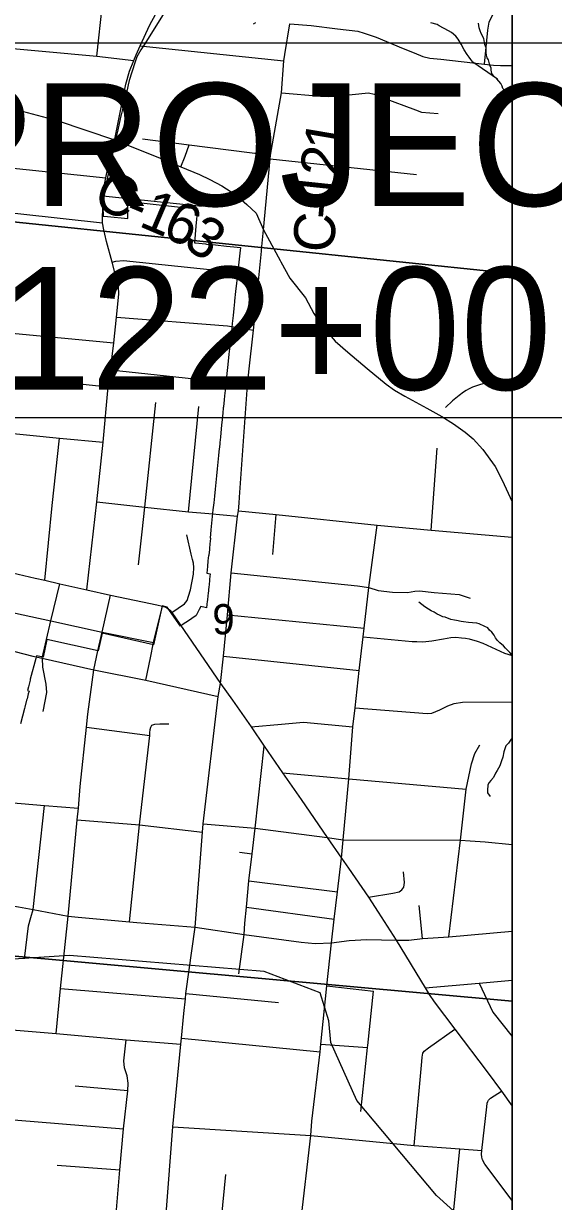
# Model space of a CAD drawing. Extents: x 0 to 43.4, y -8.1 to 22.
# Drawn here: x 8.223 to 8.957, y 18.91 to 20.543 of the extents above; entities that cross this region are included whole.
import ezdxf

# ---------------------------------------------------------------- set-up
doc = ezdxf.new("R2010")
doc.units = 0
for name, color, linetype in [('GM_X_City_Street', 7, 'Continuous'), ('GM_X_Corporation', 7, 'Continuous'), ('GM_X_County_Road', 7, 'Continuous'), ('GM_X_County_Road_Text', 7, 'Continuous'), ('GM_X_Minor_River', 7, 'Continuous'), ('GM_X_Rail_Line', 7, 'Continuous'), ('GM_X_Section_Text', 7, 'Continuous'), ('GM_X_Township_Road', 7, 'Continuous'), ('SH_Data', 7, 'Continuous'), ('SH_Masking', 7, 'Continuous'), ('SH_Text', 7, 'Continuous')]:
    doc.layers.add(name, color=color, linetype=linetype)

msp = doc.modelspace()

# ---------------------------------------------------------------- linework, layer by layer
at = {"layer": 'GM_X_City_Street'}
for p, q in [((8.3245, 20.4975), (8.3324, 20.5696)), ((8.0501, 20.3584), (8.3368, 20.329)), ((8.3516, 20.1358), (8.5054, 20.1236)), ((8.5054, 20.1236), (8.5413, 20.1177)), ((8.2021, 20.114), (8.3479, 20.1001)), ((8.1964, 20.0545), (8.34, 20.0391)), ((8.3432, 20.0626), (8.4985, 20.0459)), ((8.4985, 20.0459), (8.533, 20.0415)), ((8.4516, 19.8661), (8.4658, 20.0117)), ((8.7877, 19.8403), (8.796, 19.9541)), ((8.4796, 19.8636), (8.5194, 19.8601)), ((8.5684, 19.8069), (8.5728, 19.862)), ((8.5053, 19.7233), (8.6948, 19.7047)), ((8.3317, 19.6991), (8.403, 19.6847)), ((8.4997, 19.6657), (8.688, 19.6459)), ((8.3102, 19.5673), (8.3976, 19.5559)), ((8.5222, 19.394), (8.5396, 19.3918)), ((8.5351, 19.3543), (8.6578, 19.3389)), ((8.5317, 19.3178), (8.6532, 19.3011)), ((8.7756, 19.2742), (8.7711, 19.3203)), ((8.521, 19.2253), (8.5283, 19.28)), ((8.2739, 19.2052), (8.4471, 19.1906)), ((8.6432, 19.209), (8.7077, 19.2014)), ((8.4479, 19.1983), (8.5759, 19.1857)), ((8.4417, 19.1363), (8.6337, 19.1174)), ((8.6346, 19.128), (8.6995, 19.1232)), ((8.3671, 19.0632), (8.2945, 19.0699)), ((8.1298, 19.0296), (8.3614, 19.0105)), ((8.8182, 18.8888), (8.8272, 18.9828)), ((8.2695, 18.9603), (8.3561, 18.9538)), ((8.4972, 18.8859), (8.5029, 18.9474))]:
    msp.add_line(p, q, dxfattribs=at)
for points in [[(8.1673, 20.5121), (8.3245, 20.4975), (8.3757, 20.4914)], [(8.0437, 20.2985), (8.1053, 20.2918), (8.1602, 20.2855), (8.2192, 20.279), (8.3322, 20.2665)], [(8.3456, 20.2118), (8.3507, 20.2133), (8.3614, 20.2145), (8.4899, 20.2007)], [(7.8797, 20.0084), (7.9555, 20.0011), (8.0027, 19.996), (8.0143, 19.9949), (8.0747, 19.9886), (8.0831, 19.9878), (8.1298, 19.9827), (8.1423, 19.9812), (8.1899, 19.9763), (8.2727, 19.9678), (8.333, 19.9627)], [(8.382, 19.7925), (8.3872, 19.8384), (8.391, 19.8724), (8.406, 20.0173)], [(8.2523, 19.7711), (8.2626, 19.8747), (8.2727, 19.9678)], [(8.3244, 19.8797), (8.391, 19.8724), (8.4516, 19.8661), (8.4796, 19.8636)], [(8.6633, 19.386), (8.6659, 19.4114), (8.6734, 19.4958), (8.6791, 19.5679), (8.6821, 19.5944), (8.688, 19.6459), (8.6934, 19.6924), (8.6948, 19.7047), (8.7013, 19.7612), (8.713, 19.8473)], [(8.4285, 19.7262), (8.4457, 19.7382), (8.4496, 19.7431), (8.4516, 19.749), (8.4541, 19.7576), (8.4584, 19.7797), (8.4589, 19.7889), (8.4582, 19.7949), (8.457, 19.8), (8.4553, 19.8072), (8.4493, 19.8342)], [(8.5104, 19.7813), (8.6855, 19.7632), (8.7013, 19.7612), (8.7144, 19.7569), (8.7339, 19.7544), (8.755, 19.7542), (8.7652, 19.7559), (8.7713, 19.7563), (8.7917, 19.7542), (8.8262, 19.7513), (8.8416, 19.7464)], [(8.0439, 19.765), (8.1515, 19.7402), (8.1946, 19.7291), (8.2605, 19.7148), (8.3317, 19.6991)], [(8.2488, 19.6631), (8.2605, 19.7148), (8.2733, 19.766)], [(8.3259, 19.6733), (8.3317, 19.6991), (8.3435, 19.7504)], [(8.3921, 19.6326), (8.3988, 19.6633), (8.403, 19.6847), (8.4155, 19.7351)], [(8.0243, 19.7154), (8.1405, 19.6885), (8.1837, 19.679), (8.2356, 19.666)], [(8.6934, 19.6924), (8.7613, 19.6862), (8.7676, 19.6861), (8.776, 19.6859), (8.7885, 19.6872), (8.8048, 19.6899), (8.81, 19.6906), (8.8147, 19.6916), (8.822, 19.6921), (8.8295, 19.6914), (8.8351, 19.6907), (8.8405, 19.6899), (8.8514, 19.6867), (8.8594, 19.6838), (8.8893, 19.6701), (8.9, 19.6669)], [(8.2356, 19.666), (8.2488, 19.6631), (8.3201, 19.647), (8.3921, 19.6326), (8.4923, 19.6097)], [(8.2488, 19.6631), (8.2489, 19.6504), (8.2538, 19.627), (8.2544, 19.6156), (8.2494, 19.5893)], [(8.2678, 19.1429), (8.2739, 19.2052), (8.2845, 19.3053), (8.2971, 19.4388), (8.2988, 19.4549), (8.3012, 19.4853), (8.3102, 19.5673), (8.3117, 19.5852), (8.3201, 19.647), (8.3259, 19.6733)], [(8.6821, 19.5944), (8.7821, 19.5865), (8.7887, 19.587), (8.7996, 19.5912), (8.8109, 19.5971), (8.8193, 19.6004), (8.8311, 19.6021), (8.9, 19.6023)], [(8.3976, 19.5559), (8.3979, 19.5596), (8.3985, 19.5641), (8.3993, 19.5676), (8.4005, 19.5701), (8.4049, 19.5717), (8.4118, 19.5718), (8.4242, 19.5718)], [(8.5384, 19.5677), (8.5801, 19.5714), (8.5957, 19.5729), (8.6109, 19.5742), (8.6791, 19.5679)], [(8.3697, 19.2973), (8.3837, 19.4318), (8.3866, 19.4602), (8.3976, 19.5559)], [(8.5283, 19.28), (8.5295, 19.2955), (8.5317, 19.3178), (8.5351, 19.3543), (8.5396, 19.3918), (8.5438, 19.4273), (8.5564, 19.5412)], [(8.812, 19.2765), (8.8282, 19.4107), (8.836, 19.4814), (8.8437, 19.5165), (8.848, 19.5311), (8.8549, 19.5429)], [(8.5818, 19.5043), (8.6734, 19.4958), (8.836, 19.4814)], [(8.2035, 19.4629), (8.252, 19.459), (8.2988, 19.4549)], [(8.2241, 19.2462), (8.2297, 19.2919), (8.2327, 19.3033), (8.2363, 19.3146), (8.252, 19.459)], [(8.2971, 19.4388), (8.3837, 19.4318), (8.4707, 19.4216)], [(8.4719, 19.4333), (8.5438, 19.4273), (8.6437, 19.4144), (8.6659, 19.4114), (8.8282, 19.4107), (8.8418, 19.4099), (8.8623, 19.4082), (8.9, 19.4047)], [(8.7009, 19.3318), (8.7346, 19.3373), (8.7432, 19.3392), (8.7468, 19.342), (8.7497, 19.3455), (8.7509, 19.3519), (8.7492, 19.3667)], [(8.7793, 19.2059), (8.8541, 19.2124), (8.9, 19.2165)], [(8.8541, 19.2124), (8.873, 19.1722), (8.9, 19.1385)], [(8.6903, 19.0346), (8.6995, 19.1232), (8.6998, 19.126), (8.7077, 19.2014)], [(7.9429, 19.17), (8.0783, 19.1589), (8.1459, 19.153), (8.2678, 19.1429), (8.365, 19.134), (8.4409, 19.1278)], [(8.764, 18.9876), (8.7747, 19.1038), (8.7752, 19.11), (8.7759, 19.1156), (8.7781, 19.1181), (8.7841, 19.1228), (8.8205, 19.1487)], [(8.334, 18.7849), (8.3377, 18.7877), (8.3408, 18.7934), (8.3415, 18.7988), (8.3438, 18.8296), (8.3518, 18.8982), (8.3561, 18.9538), (8.3614, 19.0105), (8.3671, 19.0632), (8.3678, 19.0737), (8.3662, 19.0839), (8.3627, 19.095), (8.3619, 19.105), (8.365, 19.134)], [(8.9, 18.9112), (8.8621, 18.9616), (8.8587, 18.9676), (8.8578, 18.9711), (8.8575, 18.9753), (8.8579, 18.9804), (8.8646, 19.0409), (8.8654, 19.0461), (8.866, 19.0484), (8.8672, 19.0504), (8.87, 19.053), (8.8849, 19.0628)], [(8.4299, 19.0132), (8.6208, 19.0011), (8.764, 18.9876), (8.8272, 18.9828), (8.8579, 18.9804)]]:
    msp.add_lwpolyline(points, dxfattribs=at)
at = {"layer": 'GM_X_Corporation'}
for points in [[(8.9, 14.3814), (8.9, 20.9), (2.1, 20.9)], [(8.9, 17.1765), (8.9, 20.9), (4.0645, 20.9)], [(8.4199, 20.5613), (8.3907, 20.5149), (8.3854, 20.5062), (8.38, 20.4965), (8.3769, 20.4885), (8.3692, 20.4638), (8.3679, 20.4578), (8.3648, 20.4444), (8.3639, 20.4405), (8.3581, 20.4161), (8.3578, 20.4147), (8.3525, 20.3915), (8.3504, 20.3823), (8.34, 20.3337), (8.3396, 20.332), (8.3381, 20.3251), (8.3379, 20.3245), (8.3343, 20.3084), (8.3332, 20.3002), (8.3329, 20.2945), (8.3327, 20.2881), (8.333, 20.276), (8.339, 20.2754), (8.3672, 20.2725), (8.3672, 20.2791), (8.3672, 20.2817), (8.3672, 20.296), (8.3729, 20.2955), (8.436, 20.2888), (8.4472, 20.2877), (8.464, 20.286), (8.4617, 20.2618), (8.4595, 20.239), (8.461, 20.2388), (8.475, 20.2373), (8.4765, 20.2372), (8.4889, 20.2359), (8.504, 20.2344), (8.5142, 20.2333), (8.5234, 20.2322), (8.5226, 20.2244), (8.5203, 20.2036), (8.5196, 20.198), (8.5167, 20.1713), (8.5153, 20.1585), (8.5151, 20.1571), (8.5142, 20.1476), (8.5132, 20.1382), (8.512, 20.1271), (8.5108, 20.1158), (8.5095, 20.1031), (8.5075, 20.0843), (8.5065, 20.0749), (8.5041, 20.0529), (8.5029, 20.0416), (8.5022, 20.0342), (8.5018, 20.0305), (8.5014, 20.0266), (8.5008, 20.0211), (8.4998, 20.0116), (8.4996, 20.0101), (8.4989, 20.0025), (8.498, 19.9939), (8.4973, 19.9861), (8.4957, 19.9699), (8.4956, 19.9696), (8.4949, 19.9622), (8.4948, 19.9614), (8.4942, 19.9548), (8.4941, 19.9537), (8.4931, 19.9442), (8.4921, 19.9348), (8.4912, 19.9254), (8.4902, 19.916), (8.4892, 19.9066), (8.4882, 19.8971), (8.4873, 19.8877), (8.4863, 19.8783), (8.4853, 19.8689), (8.4844, 19.8596), (8.4834, 19.8502), (8.4824, 19.8408), (8.4812, 19.8295), (8.4817, 19.8295), (8.4817, 19.8288), (8.481, 19.8216), (8.4804, 19.8149), (8.4804, 19.8138), (8.4797, 19.8058), (8.4796, 19.8053), (8.4791, 19.8053), (8.4784, 19.7979), (8.4776, 19.7899), (8.4767, 19.781), (8.4814, 19.78), (8.4806, 19.7724), (8.4805, 19.771), (8.4798, 19.7648), (8.4795, 19.7619), (8.4791, 19.7578), (8.479, 19.7573), (8.4785, 19.7522), (8.4783, 19.7505), (8.4775, 19.743), (8.4774, 19.7421), (8.4764, 19.733), (8.4743, 19.7335), (8.4683, 19.7347), (8.4663, 19.7307), (8.462, 19.7221), (8.45, 19.7139), (8.4455, 19.7109), (8.4402, 19.7074), (8.4219, 19.7339), (8.4149, 19.7356), (8.4031, 19.6817), (8.3317, 19.6977), (8.3264, 19.6732), (8.2552, 19.689), (8.2499, 19.6644), (8.2407, 19.6662), (8.2398, 19.6628), (8.2322, 19.6338), (8.2319, 19.6327), (8.2295, 19.6235), (8.2281, 19.6181), (8.2306, 19.6175), (8.2294, 19.6138), (8.2277, 19.6068), (8.2271, 19.6046), (8.2247, 19.5953), (8.2243, 19.5934), (8.2188, 19.572)]]:
    msp.add_lwpolyline(points, dxfattribs=at)
for points in [[(8.9, 20.1964), (8.9, 20.9), (8.1157, 20.9), (8.0517, 20.2839)], [(8.9, 19.1875), (8.9, 20.1964), (8.0517, 20.2839), (7.955, 19.3167), (7.9506, 19.2736)], [(8.9, 18.6915), (8.9, 19.1875), (7.9506, 19.2736), (7.8526, 18.2674), (8.8482, 18.1867)]]:
    msp.add_lwpolyline(points, close=True, dxfattribs=at)
at = {"layer": 'GM_X_County_Road'}
for p, q in [((8.5848, 20.4997), (8.5917, 20.5423)), ((8.334, 20.2569), (8.3322, 20.2665)), ((8.5525, 20.2289), (8.5552, 20.2567))]:
    msp.add_line(p, q, dxfattribs=at)
for points in [[(8.3489, 20.3815), (8.3492, 20.3827), (8.3647, 20.4587), (8.3698, 20.4768), (8.3757, 20.4914), (8.3789, 20.4993), (8.3845, 20.5117), (8.3976, 20.5409), (8.4056, 20.5552), (8.4122, 20.5654)], [(8.5552, 20.2567), (8.5647, 20.3555), (8.5652, 20.3602), (8.5801, 20.4467), (8.5834, 20.4912), (8.5848, 20.4997)], [(7.8783, 20.4665), (7.8893, 20.4654), (8.198, 20.4259), (8.2071, 20.4249), (8.2207, 20.4215), (8.2693, 20.4082), (8.3489, 20.3815)], [(8.3368, 20.329), (8.3394, 20.3422), (8.3489, 20.3815)], [(8.3489, 20.3815), (8.4146, 20.3552), (8.4407, 20.3441), (8.4667, 20.3334), (8.4809, 20.3265), (8.4978, 20.3178), (8.5104, 20.3097), (8.5211, 20.3018), (8.5321, 20.2921), (8.545, 20.2799), (8.5552, 20.2567), (8.5608, 20.2467), (8.5783, 20.2144), (8.5792, 20.2126)], [(8.3878, 20.3828), (8.4524, 20.3746), (8.5652, 20.3602)], [(8.4407, 20.3441), (8.4466, 20.3589), (8.4524, 20.3746)], [(8.3327, 20.304), (8.3331, 20.3108), (8.3368, 20.329)], [(8.3322, 20.2665), (8.3321, 20.2747), (8.3325, 20.285), (8.3327, 20.304)], [(8.3103, 19.7577), (8.3244, 19.8797), (8.333, 19.9627), (8.34, 20.0391), (8.3432, 20.0626), (8.3479, 20.1001), (8.3516, 20.1358), (8.3541, 20.1586), (8.3549, 20.1683), (8.3543, 20.1776), (8.3456, 20.2118), (8.3379, 20.2409), (8.3354, 20.251), (8.334, 20.2569)], [(8.535, 20.0602), (8.5413, 20.1177), (8.5462, 20.1627), (8.5524, 20.2271), (8.5525, 20.2289)], [(8.5792, 20.2126), (8.5916, 20.1897), (8.6136, 20.1624), (8.625, 20.1408), (8.6377, 20.1223), (8.6548, 20.1025), (8.6723, 20.0871), (8.6989, 20.0646), (8.7253, 20.0429), (8.7369, 20.0348), (8.751, 20.0264), (8.7815, 20.0097), (8.8024, 19.9981), (8.8188, 19.988), (8.8346, 19.9762), (8.846, 19.9669), (8.8593, 19.9521), (8.8761, 19.9288), (8.8859, 19.9097), (8.9, 19.8799)], [(8.5214, 19.8778), (8.5221, 19.8861), (8.533, 20.0415), (8.5339, 20.0496), (8.535, 20.0602)], [(8.4959, 19.6279), (8.4997, 19.6657), (8.5053, 19.7233), (8.5104, 19.7813), (8.5194, 19.8601), (8.5205, 19.8674), (8.5214, 19.8778)], [(8.5205, 19.8674), (8.5728, 19.862), (8.713, 19.8473), (8.7877, 19.8403), (8.9, 19.8309)], [(8.1998, 19.7831), (8.2388, 19.7741), (8.2523, 19.7711), (8.2733, 19.766), (8.3103, 19.7577), (8.3435, 19.7504), (8.3876, 19.7411), (8.4077, 19.7368), (8.4155, 19.7351)], [(8.4155, 19.7351), (8.4198, 19.7337), (8.4228, 19.732), (8.4254, 19.7295), (8.4285, 19.7262)], [(8.4285, 19.7262), (8.4959, 19.6279), (8.5122, 19.6047), (8.5384, 19.5677), (8.5564, 19.5412), (8.5818, 19.5043), (8.6075, 19.4671), (8.6437, 19.4144), (8.6633, 19.386), (8.6732, 19.372), (8.7009, 19.3318), (8.7143, 19.311), (8.7392, 19.2719), (8.7793, 19.2059), (8.785, 19.1966), (8.7918, 19.1868), (8.8205, 19.1487), (8.8652, 19.0895), (8.8849, 19.0628), (8.9, 19.0421)], [(8.4088, 18.7934), (8.4206, 18.8926), (8.4299, 19.0132), (8.4409, 19.1278), (8.4417, 19.1363), (8.445, 19.1703), (8.4471, 19.1906), (8.4479, 19.1983), (8.4604, 19.2899), (8.4707, 19.4216), (8.4719, 19.4333), (8.4923, 19.6097), (8.4959, 19.6279)], [(8.5874, 18.7083), (8.6065, 18.8774), (8.6208, 19.0011), (8.6224, 19.0214), (8.6337, 19.1174), (8.6346, 19.128), (8.6432, 19.209), (8.6497, 19.2682), (8.6532, 19.3011), (8.6578, 19.3389), (8.6633, 19.386)], [(7.96, 19.3444), (8.1633, 19.325), (8.1946, 19.3219), (8.203, 19.3208), (8.2156, 19.3185), (8.2363, 19.3146), (8.2845, 19.3053), (8.2985, 19.3039), (8.3697, 19.2973), (8.3797, 19.2965)], [(8.3797, 19.2965), (8.4604, 19.2899), (8.5283, 19.28), (8.6077, 19.2695), (8.6267, 19.2675), (8.6497, 19.2682), (8.674, 19.2718), (8.6986, 19.2732), (8.7392, 19.2719)], [(8.7392, 19.2719), (8.7565, 19.272), (8.7756, 19.2742), (8.812, 19.2765), (8.9, 19.2844)]]:
    msp.add_lwpolyline(points, dxfattribs=at)
at = {"layer": 'GM_X_Minor_River'}
for points in [[(8.5442, 20.5439), (8.5411, 20.5421)], [(8.8794, 20.4655), (8.8454, 20.4891), (8.8425, 20.4929), (8.8403, 20.4961), (8.8373, 20.4999), (8.8333, 20.5065), (8.829, 20.5143), (8.825, 20.5212), (8.8217, 20.5251), (8.8157, 20.5302), (8.8116, 20.5327), (8.7988, 20.5395), (8.7959, 20.5415), (8.7872, 20.544)], [(8.9, 20.4402), (8.8952, 20.445), (8.887, 20.4529), (8.8859, 20.4559), (8.8841, 20.4598), (8.8786, 20.4664), (8.8738, 20.4704), (8.8716, 20.4738), (8.871, 20.4781), (8.871, 20.4811), (8.8689, 20.485), (8.8672, 20.4923), (8.865, 20.4954), (8.8643, 20.4992), (8.864, 20.5022), (8.8638, 20.5091), (8.862, 20.5137), (8.8604, 20.5221), (8.8571, 20.5291), (8.8557, 20.5329), (8.8543, 20.5368), (8.8533, 20.5433)], [(8.9, 20.0492), (8.8947, 20.0486), (8.8878, 20.048), (8.884, 20.0477), (8.8798, 20.0475), (8.8756, 20.0468), (8.8703, 20.0462), (8.8653, 20.0452), (8.8592, 20.0435), (8.8546, 20.0421), (8.845, 20.0385), (8.8392, 20.036), (8.8361, 20.0342), (8.8326, 20.0317), (8.8264, 20.0273), (8.8218, 20.0236), (8.8171, 20.0199), (8.8073, 20.0107)], [(8.9, 19.6671), (8.8996, 19.6676), (8.8966, 19.6707), (8.894, 19.6738), (8.8907, 19.677), (8.8877, 19.6801), (8.8829, 19.6844), (8.8796, 19.6876), (8.877, 19.6911), (8.8748, 19.6949), (8.8715, 19.6992), (8.8686, 19.702), (8.866, 19.7051), (8.8619, 19.7071), (8.854, 19.7108), (8.851, 19.7116), (8.8449, 19.7122), (8.8392, 19.7123), (8.8324, 19.7133), (8.8293, 19.7137), (8.8229, 19.7151), (8.8199, 19.7155), (8.815, 19.7168), (8.8071, 19.7197), (8.804, 19.7205), (8.7992, 19.7226), (8.7958, 19.7242), (8.7917, 19.7266), (8.7875, 19.7286), (8.7838, 19.731), (8.7789, 19.7342), (8.7745, 19.7374), (8.7704, 19.7405)], [(8.9, 19.5521), (8.8987, 19.5507), (8.8947, 19.5451), (8.8912, 19.5414), (8.8896, 19.5372), (8.8883, 19.5331), (8.887, 19.5259), (8.8853, 19.5206), (8.8829, 19.5138), (8.8793, 19.5071), (8.8769, 19.5037), (8.8741, 19.4977), (8.8705, 19.4936), (8.8682, 19.4906), (8.8662, 19.4876), (8.8656, 19.4796), (8.8659, 19.4762), (8.8695, 19.4711)]]:
    msp.add_lwpolyline(points, dxfattribs=at)
at = {"layer": 'GM_X_Rail_Line'}
msp.add_lwpolyline([(8.9, 18.8236), (8.795, 18.9182), (8.6846, 19.0496), (8.6488, 19.1303), (8.6458, 19.1601), (8.6339, 19.1989), (8.5563, 19.2288), (8.2864, 19.2507), (8.1872, 19.2443), (8.0986, 19.2232), (8.01, 19.2211), (7.9298, 19.2211), (7.7314, 19.2507)], dxfattribs=at)
at = {"layer": 'GM_X_Township_Road'}
for p, q in [((8.3845, 20.5117), (8.5834, 20.4912)), ((8.5647, 20.3555), (8.7672, 20.3335)), ((8.3327, 20.304), (8.4702, 20.2896))]:
    msp.add_line(p, q, dxfattribs=at)
for points in [[(8.8614, 20.4865), (8.8663, 20.5338), (8.8678, 20.5446), (8.872, 20.5536), (8.8812, 20.5693), (8.8871, 20.5819), (8.8897, 20.5934), (8.8915, 20.6106)], [(8.5917, 20.5423), (8.6212, 20.5402), (8.6577, 20.5356), (8.6862, 20.5323), (8.6949, 20.5295), (8.7112, 20.5241), (8.7489, 20.5084), (8.7639, 20.5022)], [(8.7639, 20.5022), (8.7762, 20.4971), (8.7856, 20.4948), (8.8011, 20.4935), (8.8614, 20.4865), (8.8739, 20.4851), (8.8838, 20.4846), (8.9, 20.4845)], [(8.5801, 20.4467), (8.6345, 20.4421), (8.6455, 20.4416), (8.6603, 20.4425), (8.7009, 20.4467), (8.7085, 20.4451), (8.7213, 20.44), (8.7659, 20.4232), (8.7742, 20.4201), (8.7973, 20.4179)]]:
    msp.add_lwpolyline(points, dxfattribs=at)
at = {"layer": 'SH_Data'}
msp.add_line((8.9, 20.9), (8.9, 14.1), dxfattribs=at)
at = {"layer": 'SH_Masking'}
msp.add_lwpolyline([(7.4161, 20.5159), (9.1735, 20.5159), (9.1735, 19.9964), (7.4161, 19.9964)], close=True, dxfattribs=at)
at = {"layer": 'SH_Text'}
msp.add_lwpolyline([(7.4161, 20.5159), (9.1735, 20.5159), (9.1735, 19.9964), (7.4161, 19.9964)], close=True, dxfattribs=at)

# ---------------------------------------------------------------- texts
at = {"layer": 'GM_X_County_Road_Text'}
for s, rotation, p in [('1', 80.3272, (8.6662, 20.3617)), ('2', 82.813, (8.6619, 20.3277)), ('C', 336.9534, (8.3165, 20.2902)), ('1', 83.9872, (8.6583, 20.2932)), ('1', 336.8978, (8.3809, 20.2627)), ('-', 336.9411, (8.3595, 20.2719)), ('6', 334.8629, (8.4126, 20.2492)), ('-', 84.5648, (8.6561, 20.2701)), ('3', 324.229, (8.4419, 20.2358)), ('C', 84.7498, (8.6518, 20.2237))]:
    msp.add_text(s, height=0.0568, rotation=rotation, dxfattribs=at).set_placement(p)
at = {"layer": 'GM_X_Section_Text'}
msp.add_text('9', height=0.0419, rotation=0, dxfattribs=at).set_placement((8.4843, 19.6961))
at = {"layer": 'SH_Text'}
for s, p in [('END PROJECT', (7.5415, 20.2901)), ('STA. 122+00', (7.6213, 20.0351))]:
    msp.add_text(s, height=0.17, dxfattribs=at).set_placement(p)

doc.saveas('drawing.dxf')
